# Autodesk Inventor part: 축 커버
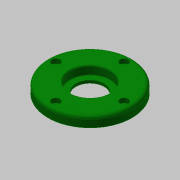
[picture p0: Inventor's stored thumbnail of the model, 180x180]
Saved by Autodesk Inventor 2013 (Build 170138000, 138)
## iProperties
Created: 2015-10
Part Number: 축 커버
Document SubType Name: Modeling
Designer: mdu
Density: 1 g/cm^3
Material: 일반
Mass: 42.4472 g
Surface Area: 136.578 cm^2
Volume: 42.4472 cm^3
Author: mdu
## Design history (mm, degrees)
sketch "스케치1"
  geometry: C1 r 40 at (0, 0) reference; C2 r 26 at (0, 0) reference; 1 further point
  node "참조1"
  node "참조2"
extrude "돌출1" new body sketch "스케치1" distance "d0" = 10; taper "d1" = 0 deg
extrude "돌출2" join sketch "스케치1" distance "d2" = 4; taper "d3" = 0 deg
hole "구멍1" diameter "d6" = 27; stored, may be unused: countersink angle "d10" = 90 deg, drill point angle "d12" = 118 deg; dims "d7" = 6, "d8" = 38, "d9" = 8.3, "d11" = 8, "d33" = 10, "d34" = 10
sketch "스케치2"
  geometry: C1 r 20 at (0, 0); 1 further point
  constraints: 1 centre point, 1 coincident
  dimensions: "d13" = 40 diameter of C1
extrude "돌출3" cut sketch "스케치2" distance "d14" = 3; taper "d15" = 0 deg
sketch "스케치3"
  geometry: C1 r 1.621 at (0, 32.5) reference; 1 further point
hole "구멍2" sketch "스케치3" at (0, 32.5) diameter "d16" = 4.5; stored, may be unused: countersink angle "d20" = 90 deg, drill point angle "d22" = 118 deg; dims "d17" = 6, "d18" = 8, "d19" = 4.4, "d21" = 8
fillet "모깎기1" dims "d26" = 3, "d27" = 0.3
chamfer "모따기1" distance "d28" = 1; stored, may be unused: second distance "d29" = 2, angle "d30" = 45 deg
chamfer "모따기2" distance "d31" = 0.8; stored, may be unused: second distance "d32" = 2, angle "d35" = 30 deg
node "솔리드1"
pattern_circular "원형 패턴1" dims angle "d24" = 360 deg
node "참조3"
